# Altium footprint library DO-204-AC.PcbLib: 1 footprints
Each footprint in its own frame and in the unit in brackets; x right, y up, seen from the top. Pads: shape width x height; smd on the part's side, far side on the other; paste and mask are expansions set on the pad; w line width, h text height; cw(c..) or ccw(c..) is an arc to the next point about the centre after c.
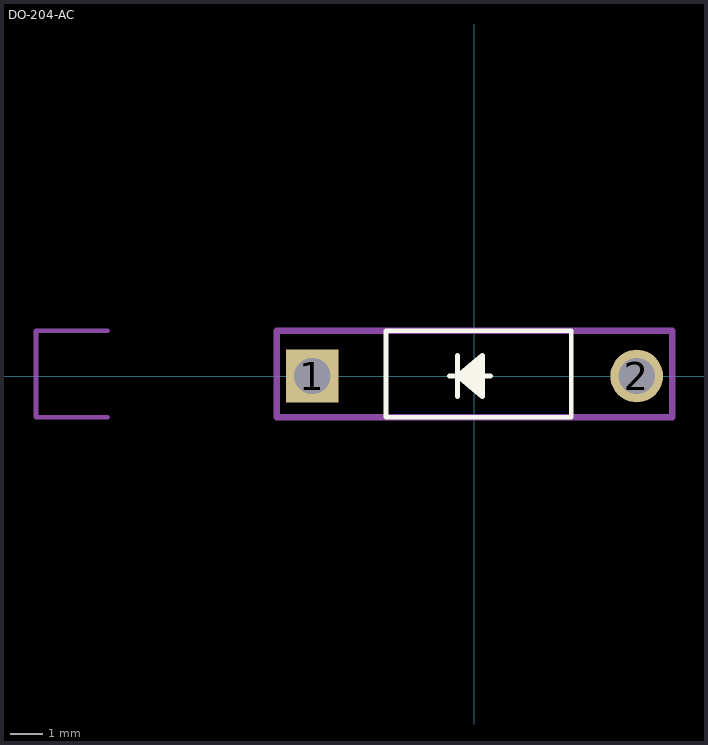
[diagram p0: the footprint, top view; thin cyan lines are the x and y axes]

## DO-204-AC [mil]
pads (2):
  rect 64x64 hole 44: 1(-196.85,0)
  round 64 hole 44: 2(196.85,0)
Top Overlay:
  lines w6: -30.5,0 19.5,0 ; -20.5,-25 -20.5,25 ; 9.5,-20 -20.5,0 ; 9.5,-15 -20.5,0 ; 9.5,-10 -20.5,0 ; 9.5,-5 -20.5,0 ; 9.5,5 -20.5,0 ; 9.5,10 -20.5,0 ; 9.5,15 -20.5,0 ; 9.5,20 -20.5,0 ; -20.5,0 9.5,-25 9.5,25 -20.5,0 ; -107.5,-50 117.5,-50 117.5,55 -107.5,55 -107.5,-50
Mechanical 15:
  lines w6: -445.5,-50 -532.5,-50 -532.5,55 -445.5,55
  lines w7.87: -60,55 240,55 ; 240,55 -240,55 -240,-50 240,-50 240,55
3D body "User Library-DO-41 10mm.step": height 171.73, standoff -39.37, extent -211.44,-53.64 216.12,53.64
